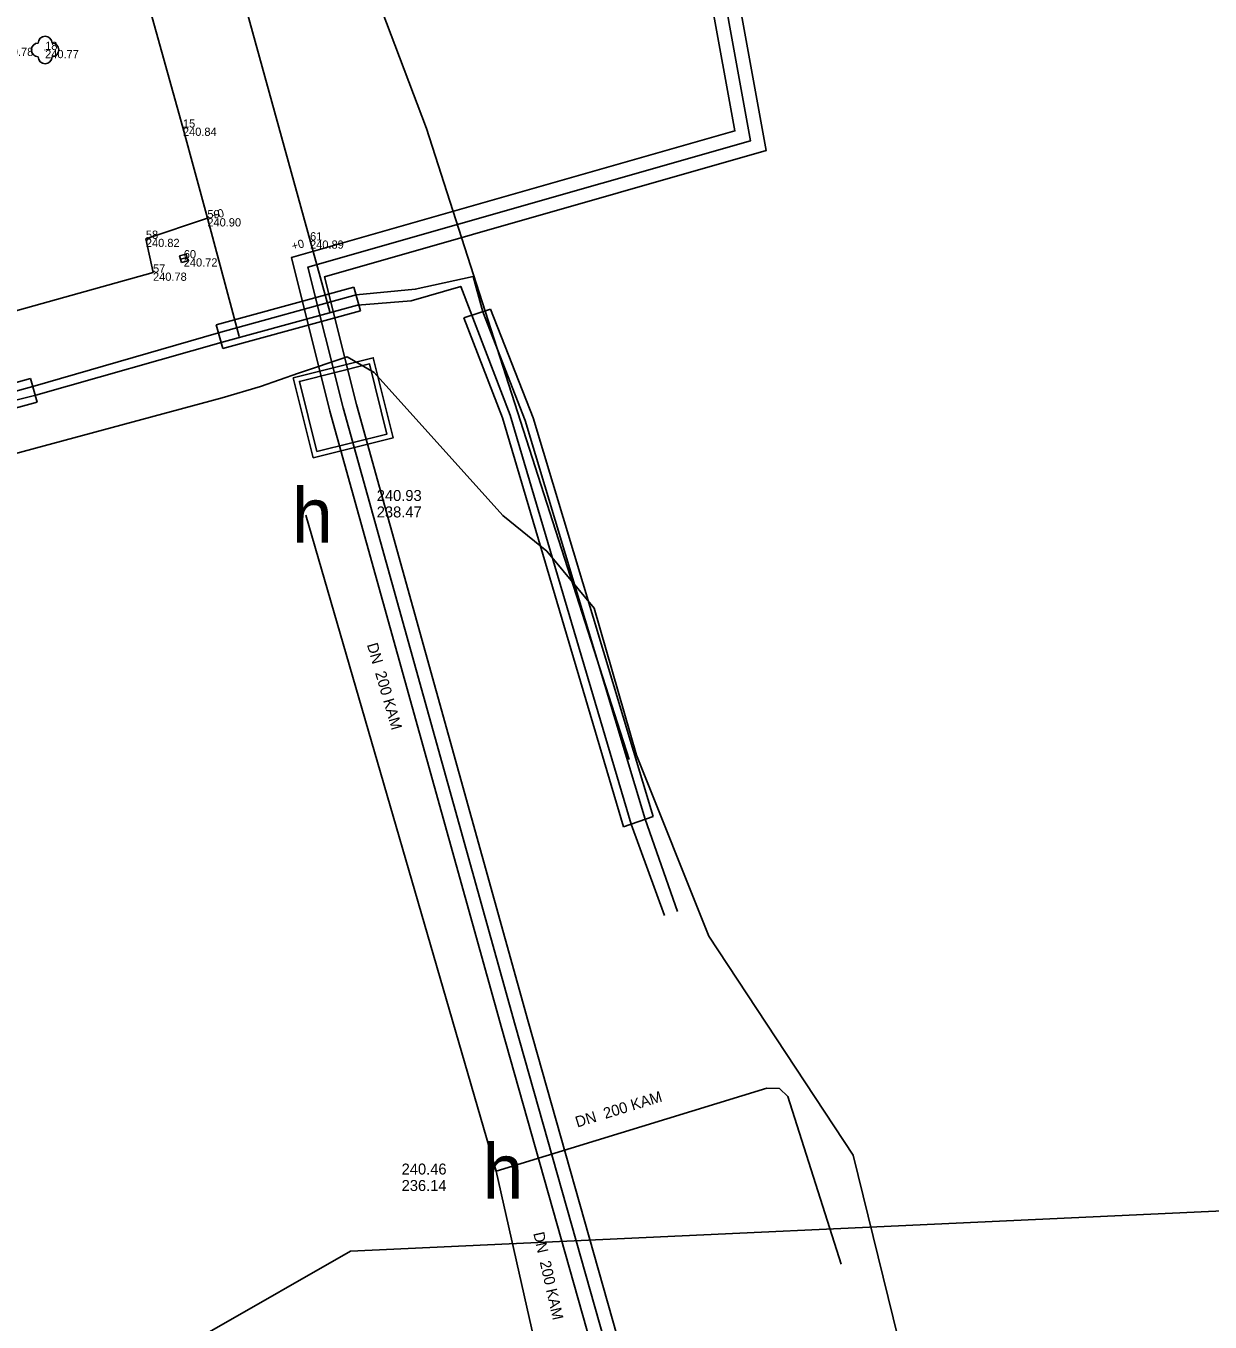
# Model space of a CAD drawing. Extents: x -599432 to -598680, y -1159407 to -1158632.
# Drawn here: x -598982.3 to -598939.17, y -1158945.72 to -1158898.5 of the extents above; entities that cross this region are included whole.
import ezdxf

# ---------------------------------------------------------------- set-up
doc = ezdxf.new("R2010")
doc.units = 0
for name, color, linetype in [('0004 VY - Body podrobné', 7, 'Continuous'), ('0005 VY - Body podrobné - čísla', 7, 'Continuous'), ('0006 VY - Body podrobné - výšky', 7, 'Continuous'), ('0027 ZA - Silnice_cesta zpevněná', 7, 'Continuous'), ('0030 ZA - Chodník', 7, 'Continuous'), ('0031 ZA - Ostatní rozhraní', 7, 'Continuous'), ('0035 ZA - Strom - značka', 7, 'Continuous'), ('0073 TE - Výška obrubníků a zdí', 7, 'Continuous'), ('0075 ZA - BVK - kanalizace - buňky', 7, 'Continuous'), ('0200 PV - BVK - kanalizace - buňky', 7, 'Continuous'), ('0201 PV - BVK - kanalizace - popis', 7, 'Continuous'), ('0207 PV - BVK - kanalizace - jednotná přípojka', 7, 'Continuous'), ('0250 PV - TB - buňky', 7, 'Continuous'), ('0254 PV - TB - horkovod - vedení', 7, 'Continuous'), ('0255 PV - TB - horkovod - okraj', 7, 'Continuous'), ('0354 PV - EON - VN', 7, 'Continuous'), ('0367 PV - EON - VN chránička', 7, 'Continuous'), ('0502 PV - UPC - vedení', 7, 'Continuous'), ('0552 PV - OT VUT', 7, 'Continuous')]:
    doc.layers.add(name, color=color, linetype=linetype)

msp = doc.modelspace()

# ---------------------------------------------------------------- linework, layer by layer
at = {"layer": '0004 VY - Body podrobné'}
for p, q in [((-598981.6, -1158899.38), (-598981.6, -1158899.38)), ((-598976.58, -1158902.21), (-598976.58, -1158902.21)), ((-598975.69, -1158905.51), (-598975.69, -1158905.51)), ((-598977.93, -1158906.26), (-598977.93, -1158906.26)), ((-598971.95, -1158906.32), (-598971.95, -1158906.32)), ((-598976.55, -1158906.97), (-598976.55, -1158906.97)), ((-598977.67, -1158907.49), (-598977.67, -1158907.49))]:
    msp.add_line(p, q, dxfattribs=at)
at = {"layer": '0027 ZA - Silnice_cesta zpevněná'}
for p, q in [((-598976.58, -1158902.21), (-598981.06, -1158886.11)), ((-598971.235, -1158908.915), (-598976.56, -1158889.58)), ((-598975.69, -1158905.51), (-598976.58, -1158902.21))]:
    msp.add_line(p, q, dxfattribs=at)
at = {"layer": '0030 ZA - Chodník'}
for p, q in [((-598977.93, -1158906.26), (-598975.69, -1158905.51)), ((-598977.67, -1158907.49), (-598977.93, -1158906.26)), ((-599001.82, -1158914.24), (-598977.67, -1158907.49))]:
    msp.add_line(p, q, dxfattribs=at)
at = {"layer": '0031 ZA - Ostatní rozhraní'}
msp.add_line((-598974.527, -1158909.822), (-598975.69, -1158905.51), dxfattribs=at)
at = {"layer": '0035 ZA - Strom - značka'}
msp.add_circle((-598981.6, -1158899.38), 0.00025, dxfattribs=at)
for centre, start, end in [((-598981.6, -1158899.13), 0, 180), ((-598981.85, -1158899.38), 90, 270), ((-598981.35, -1158899.38), 270, 90), ((-598981.6, -1158899.63), 180, 360)]:
    msp.add_arc(centre, 0.25, start, end, dxfattribs=at)
at = {"layer": '0075 ZA - BVK - kanalizace - buňky'}
msp.add_line((-598976.671, -1158907.003), (-598976.429, -1158906.937), dxfattribs=at)
msp.add_lwpolyline([(-598976.638, -1158907.123), (-598976.397, -1158907.058), (-598976.462, -1158906.817), (-598976.703, -1158906.882)], close=True, dxfattribs=at)
at = {"layer": '0207 PV - BVK - kanalizace - jednotná přípojka'}
for p in [(-598972.11, -1158916.33), (-598972.11, -1158916.33), (-598963.175, -1158949.094), (-598963.175, -1158949.094)]:
    msp.add_line(p, (-598965.17, -1158940.23), dxfattribs=at)
msp.add_lwpolyline([(-598965.17, -1158940.23), (-598955.312, -1158937.201), (-598954.852, -1158937.213), (-598954.547, -1158937.502), (-598952.609, -1158943.615)], dxfattribs=at)
msp.add_lwpolyline([(-598965.17, -1158940.23), (-598955.312, -1158937.201), (-598954.852, -1158937.213), (-598954.547, -1158937.502), (-598952.609, -1158943.615)], dxfattribs=at)
at = {"layer": '0250 PV - TB - buňky'}
for points in [[(-598972.564, -1158911.32), (-598969.648, -1158910.592), (-598968.92, -1158913.509), (-598971.836, -1158914.236), (-598972.564, -1158911.32)], [(-598971.7, -1158914.009), (-598969.148, -1158913.372), (-598969.785, -1158910.82), (-598972.337, -1158911.457), (-598971.7, -1158914.009)]]:
    msp.add_lwpolyline(points, dxfattribs=at)
at = {"layer": '0254 PV - TB - horkovod - vedení'}
for points in [[(-598941.886, -1158857.475), (-598942.314, -1158857.603), (-598941.055, -1158862.095), (-598952.358, -1158865.334), (-598962.225, -1158867.921), (-598955.905, -1158902.685), (-598972.026, -1158907.292), (-598970.745, -1158912.415)], [(-598970.745, -1158912.415), (-598964.482, -1158934.911), (-598961.242, -1158946.376), (-598955.875, -1158964.415)]]:
    msp.add_lwpolyline(points, dxfattribs=at)
at = {"layer": '0255 PV - TB - horkovod - okraj'}
for points in [[(-598942.756, -1158857.213), (-598942.928, -1158857.265), (-598941.671, -1158861.751), (-598952.49, -1158864.852), (-598962.8, -1158867.555), (-598956.478, -1158902.329), (-598972.628, -1158906.944), (-598971.23, -1158912.536)], [(-598941.111, -1158862.632), (-598952.226, -1158865.816), (-598961.65, -1158868.287), (-598955.332, -1158903.041), (-598971.424, -1158907.64), (-598970.26, -1158912.294)], [(-598971.23, -1158912.536), (-598964.964, -1158935.045), (-598961.722, -1158946.515), (-598956.354, -1158964.558)], [(-598970.26, -1158912.294), (-598964, -1158934.777), (-598960.762, -1158946.237), (-598955.396, -1158964.272)]]:
    msp.add_lwpolyline(points, dxfattribs=at)
at = {"layer": '0354 PV - EON - VN'}
for points in [[(-599006.59, -1158917.29), (-599006.35, -1158917.98), (-599006.129, -1158918.288), (-599005.159, -1158918.185), (-599001.402, -1158917.053), (-598998.856, -1158916.355), (-598985.07, -1158912.464), (-598982.051, -1158911.635), (-598975.289, -1158909.683), (-598970.276, -1158908.305), (-598968.116, -1158908.1), (-598966.007, -1158907.633), (-598965.658, -1158908.92), (-598964.11, -1158912.874), (-598959.74, -1158927.397), (-598958.572, -1158930.77)], [(-598959.038, -1158930.908), (-598960.249, -1158927.586), (-598964.661, -1158912.685), (-598966.461, -1158907.996), (-598968.262, -1158908.523), (-598970.219, -1158908.674), (-598975.102, -1158910.015), (-598981.938, -1158911.955), (-598984.941, -1158912.71), (-598998.798, -1158916.71), (-599000.994, -1158917.328), (-599001.352, -1158917.409), (-599001.565, -1158917.818)]]:
    msp.add_lwpolyline(points, dxfattribs=at)
at = {"layer": '0367 PV - EON - VN chránička'}
for p, q in [((-598975.369, -1158909.394), (-598970.356, -1158908.016)), ((-598970.356, -1158908.016), (-598970.116, -1158908.883)), ((-598966.346, -1158909.133), (-598965.373, -1158908.826)), ((-598965.373, -1158908.826), (-598963.826, -1158912.776)), ((-598970.116, -1158908.883), (-598975.129, -1158910.261)), ((-598964.945, -1158912.781), (-598966.346, -1158909.133)), ((-598975.129, -1158910.261), (-598975.369, -1158909.394)), ((-598985.149, -1158912.175), (-598982.13, -1158911.346)), ((-598982.13, -1158911.346), (-598981.893, -1158912.213)), ((-598981.893, -1158912.213), (-598984.912, -1158913.042)), ((-598960.534, -1158927.68), (-598964.945, -1158912.781)), ((-598963.826, -1158912.776), (-598959.454, -1158927.305)), ((-598959.454, -1158927.305), (-598960.534, -1158927.68))]:
    msp.add_line(p, q, dxfattribs=at)
at = {"layer": '0502 PV - UPC - vedení'}
msp.add_lwpolyline([(-598974.221, -1158885.039), (-598967.71, -1158902.237), (-598960.33, -1158925.23)], dxfattribs=at)
at = {"layer": '0552 PV - OT VUT'}
for points in [[(-598949.8, -1158949.27), (-598952.17, -1158939.64), (-598957.42, -1158931.66), (-598960.06, -1158925.07), (-598961.6, -1158919.72), (-598963.32, -1158917.64), (-598964.93, -1158916.34), (-598969.61, -1158911.13), (-598970.6, -1158910.56), (-598972.37, -1158911.15), (-598973.76, -1158911.64), (-598975.15, -1158912.05), (-598984.57, -1158914.59), (-598985.31, -1158914.84), (-598987.53, -1158915.45), (-598988.02, -1158914.4), (-598988.85, -1158912.53), (-598989.34, -1158911.46), (-598989.82, -1158910.38), (-598991.34, -1158906.42), (-598994.13, -1158899.16)], [(-598811.198, -1158926.789), (-598834.84, -1158929.91), (-598874.35, -1158938.69), (-598970.48, -1158943.14), (-598980.75, -1158949.02), (-599039.91, -1158982.96), (-599045.9, -1158984.32)]]:
    msp.add_lwpolyline(points, dxfattribs=at)

# ---------------------------------------------------------------- texts
at = {"layer": '0005 VY - Body podrobné - čísla'}
for s, p in [('18', (-598981.6, -1158899.38)), ('15', (-598976.58, -1158902.21)), ('59', (-598975.69, -1158905.51)), ('58', (-598977.93, -1158906.26)), ('61', (-598971.95, -1158906.32)), ('60', (-598976.55, -1158906.97)), ('57', (-598977.67, -1158907.49))]:
    msp.add_text(s, height=0.3, dxfattribs=at).set_placement(p)
at = {"layer": '0006 VY - Body podrobné - výšky'}
for s, p in [('240.78', (-598983.26, -1158899.6)), ('240.77', (-598981.6, -1158899.68)), ('240.84', (-598976.58, -1158902.51)), ('240.90', (-598975.69, -1158905.81)), ('240.82', (-598977.93, -1158906.56)), ('240.89', (-598971.95, -1158906.62)), ('240.72', (-598976.55, -1158907.27)), ('240.78', (-598977.67, -1158907.79))]:
    msp.add_text(s, height=0.3, dxfattribs=at).set_placement(p)
at = {"layer": '0073 TE - Výška obrubníků a zdí'}
for p in [(-598975.498, -1158905.565), (-598972.577, -1158906.679)]:
    msp.add_text('+0', height=0.3, rotation=15.1896, dxfattribs=at).set_placement(p)
at = {"layer": '0200 PV - BVK - kanalizace - buňky'}
for p in [(-598972.61, -1158917.33), (-598965.67, -1158941.23)]:
    msp.add_text('h', height=2, dxfattribs=at).set_placement(p)
at = {"layer": '0201 PV - BVK - kanalizace - popis'}
for s, p in [('240.93', (-598969.521, -1158915.811)), ('238.47', (-598969.521, -1158916.411)), ('240.46', (-598968.615, -1158940.349)), ('236.14', (-598968.615, -1158940.949))]:
    msp.add_text(s, height=0.4, dxfattribs=at).set_placement(p)
for rotation, p in [(286.1924, (-598969.883, -1158921.045)), (17.0741, (-598962.218, -1158938.639)), (282.6974, (-598963.822, -1158942.488))]:
    msp.add_text('DN  200 KAM', height=0.4, rotation=rotation, dxfattribs=at).set_placement(p)

doc.saveas('drawing.dxf')
